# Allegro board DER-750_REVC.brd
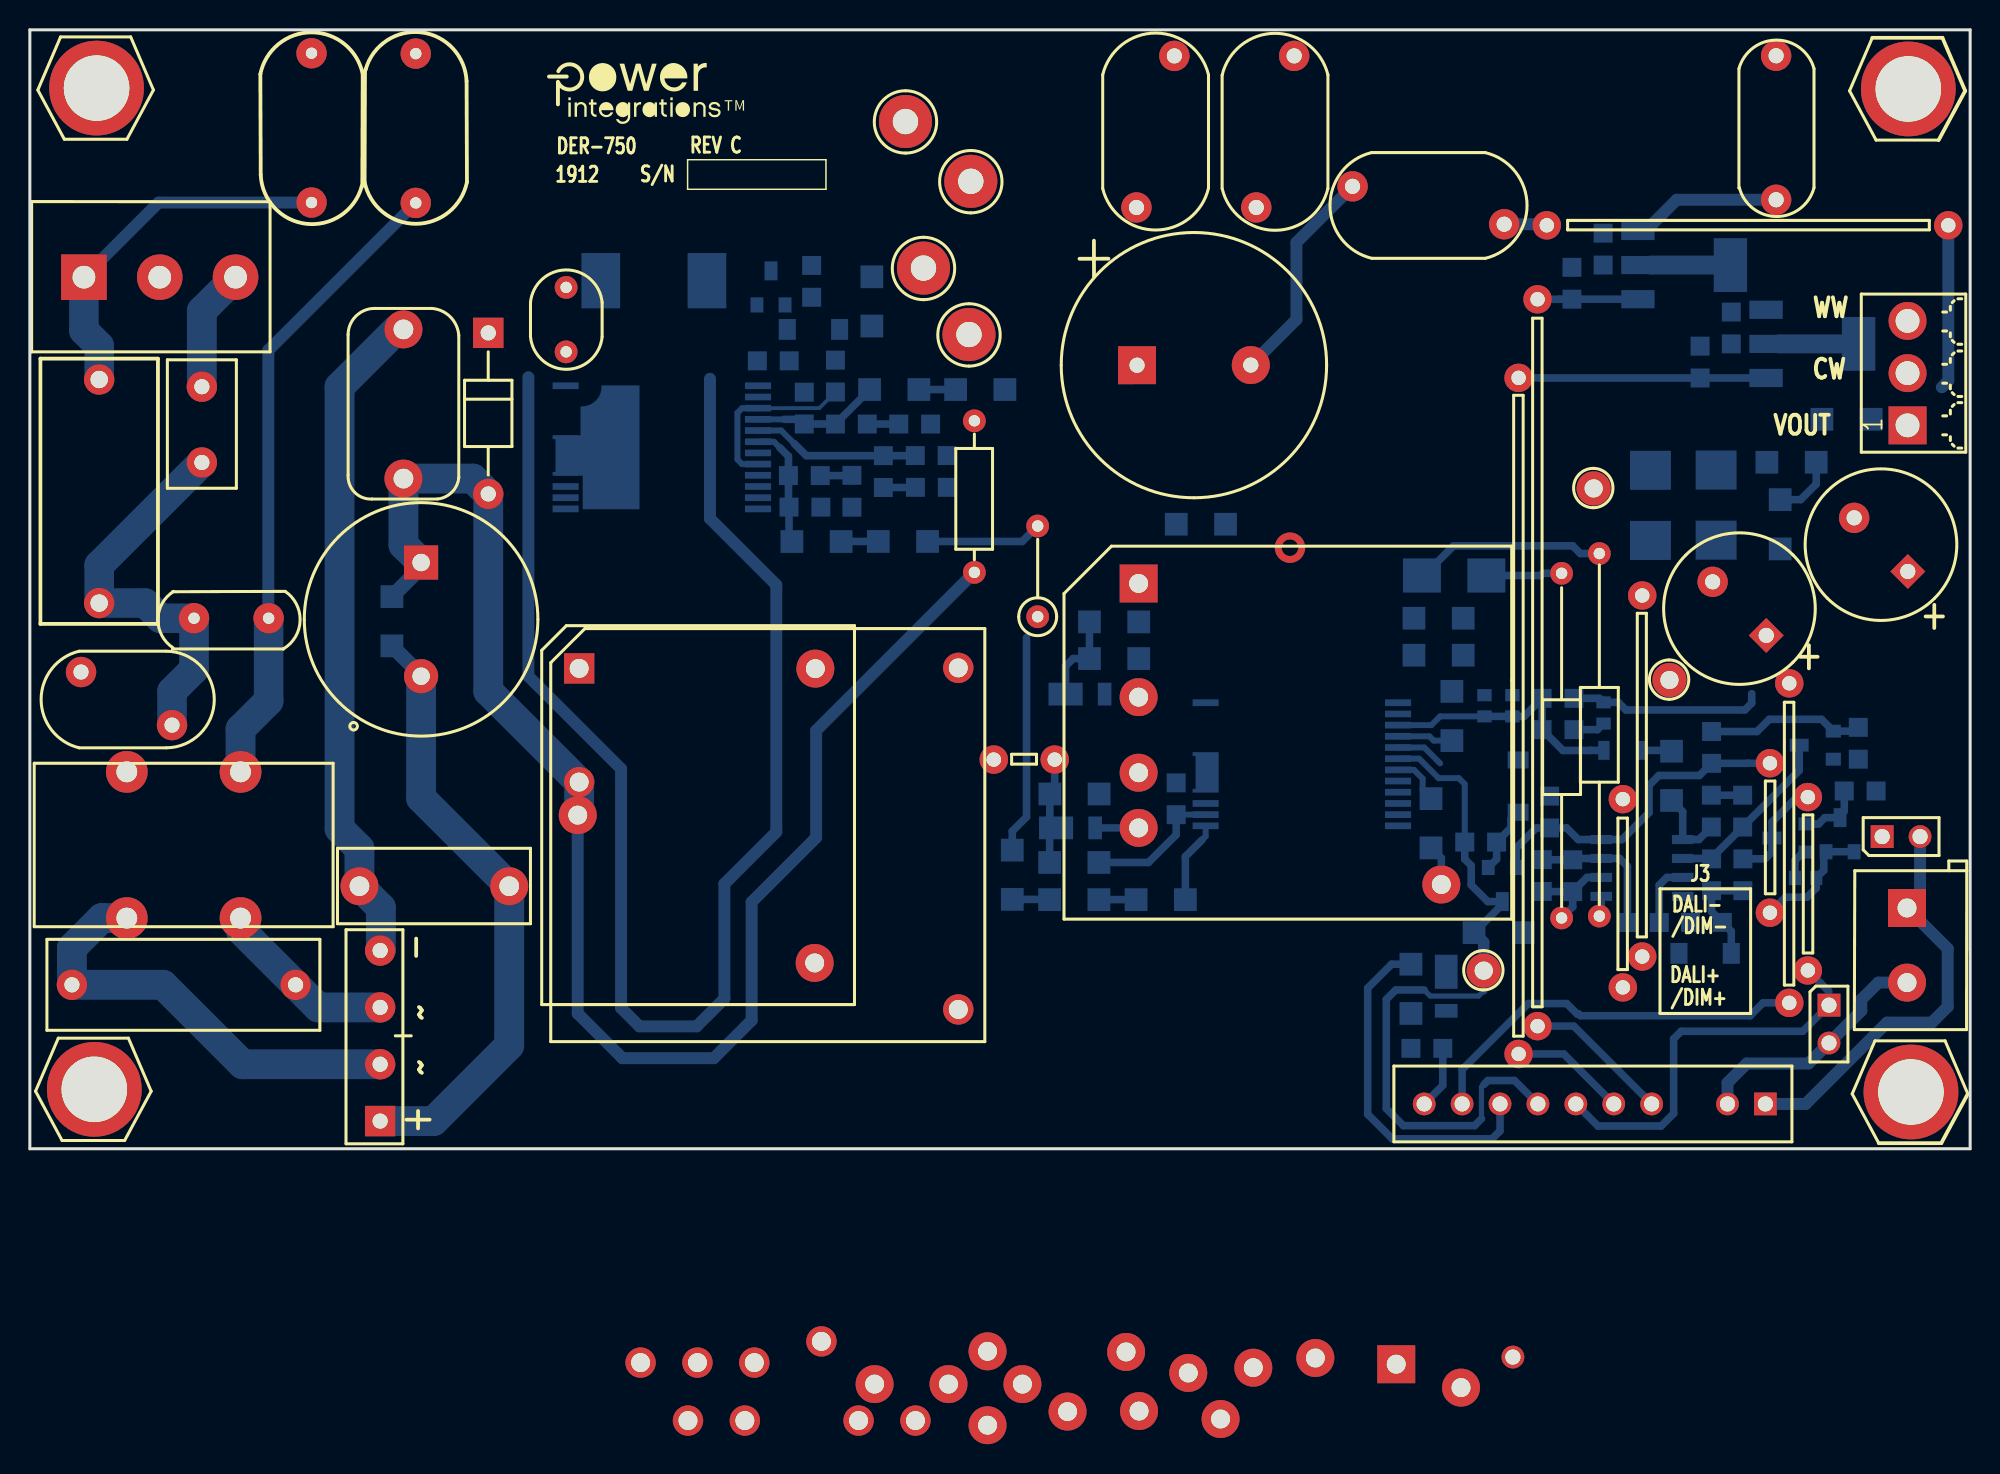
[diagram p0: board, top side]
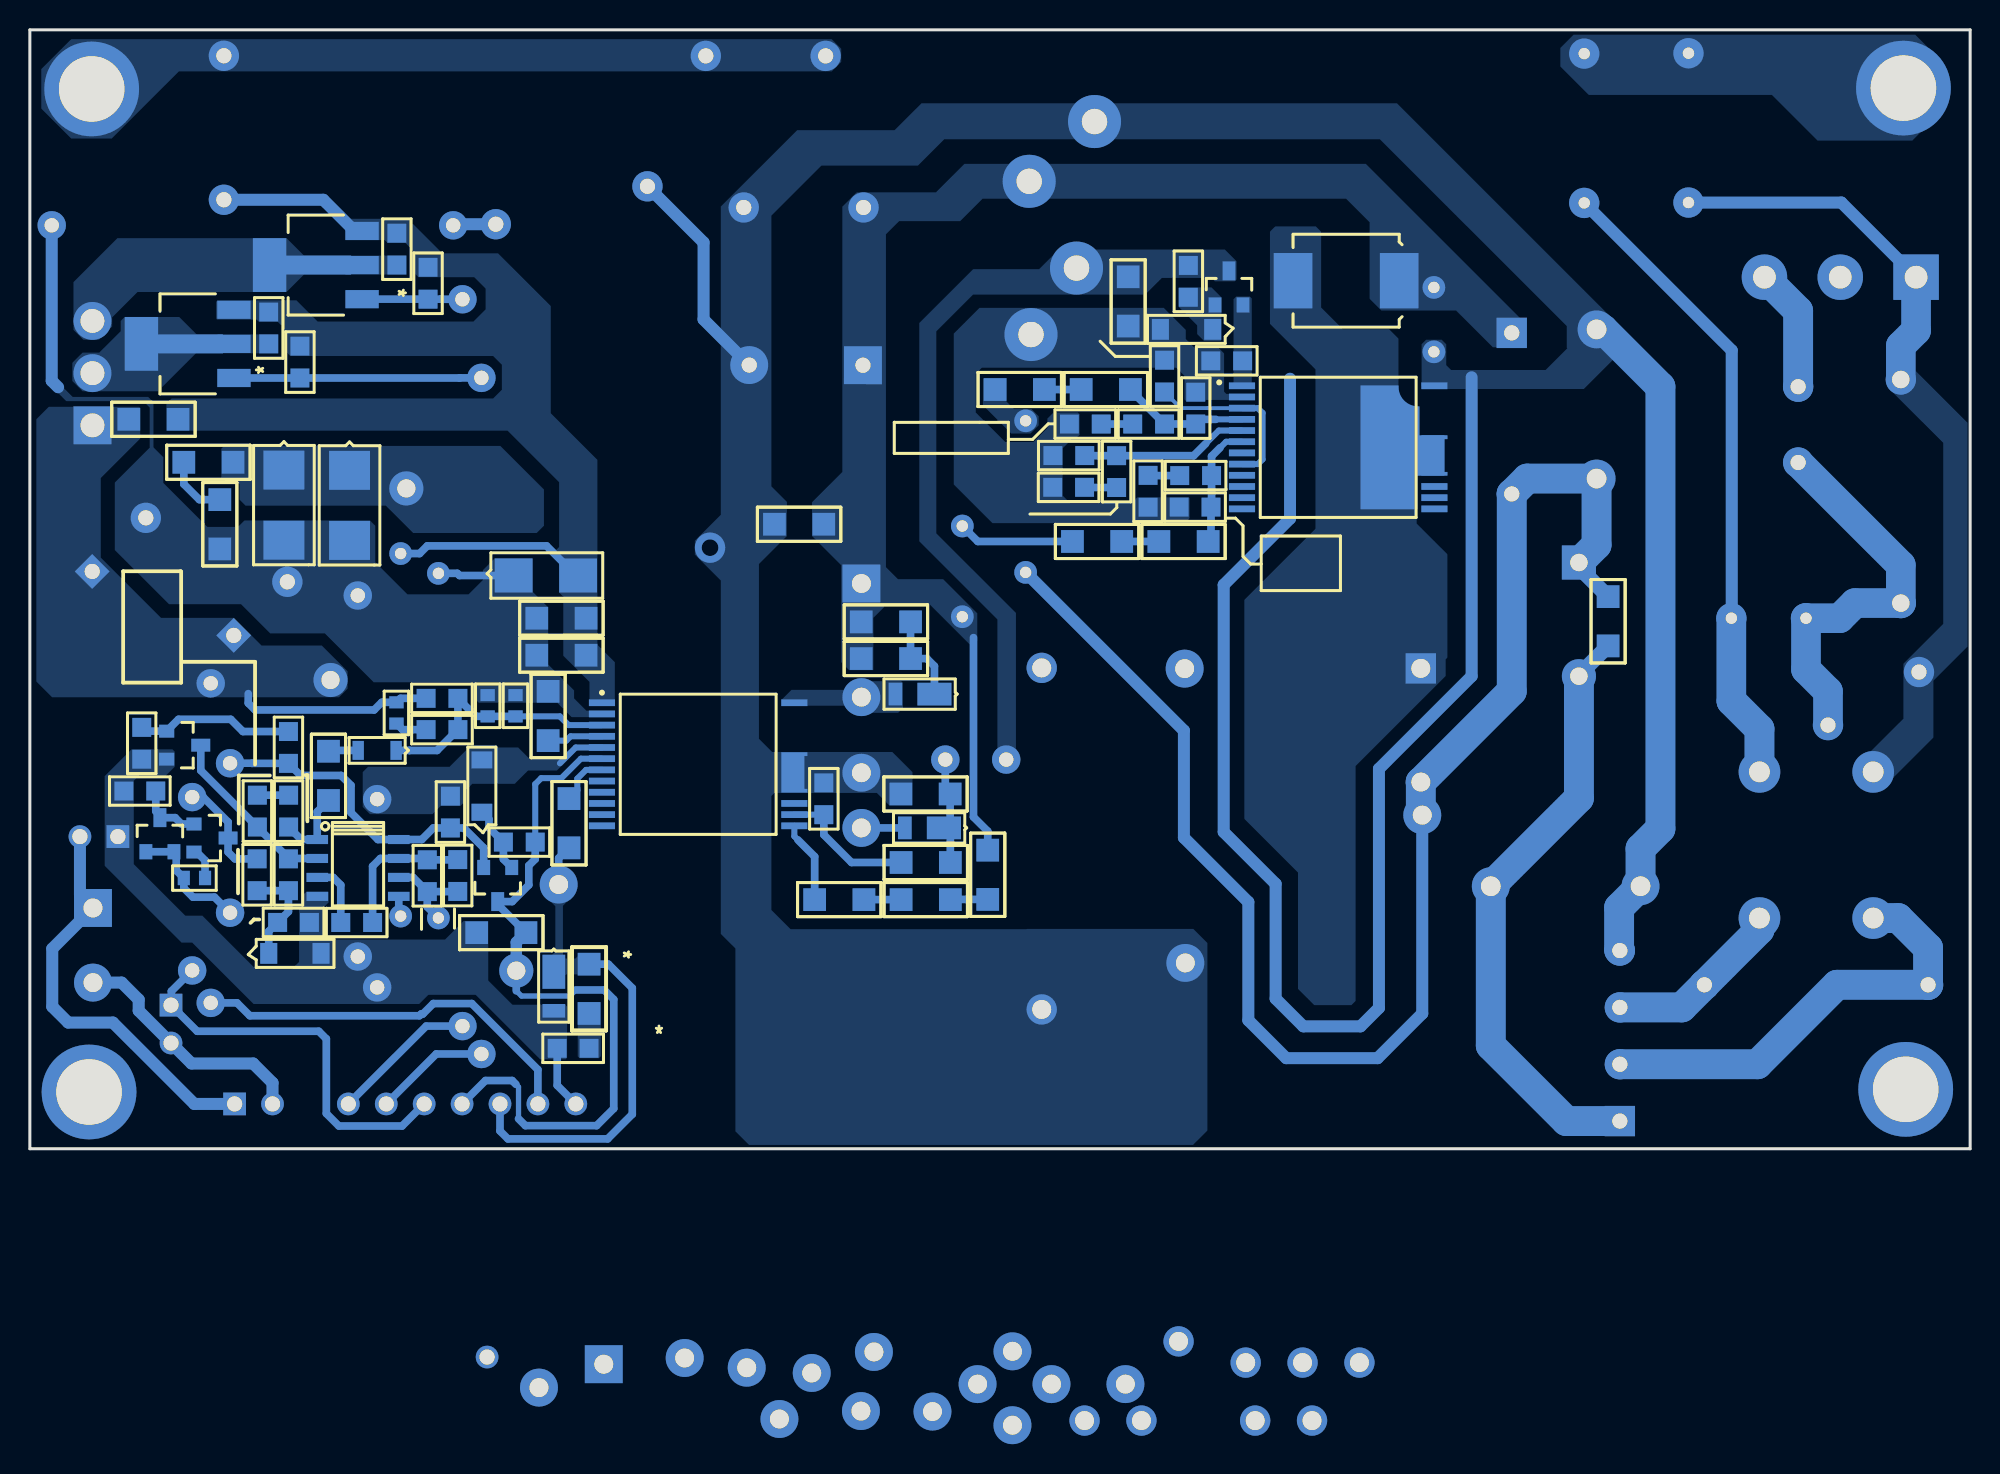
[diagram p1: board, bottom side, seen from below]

Outline 130 x 75 mm; copper layers: TOP, BOTTOM. Coordinates in mm from the lower left corner of the outline.
Outline path: 0,75 130,75 130,0 0,0 0,75

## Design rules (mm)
constraint set DEFAULT: min track width 0.508

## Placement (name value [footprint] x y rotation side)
BR1  UD4KB100-BP  [PIDAXBRIDGED3K]  23.47 1.85 90 top
C1  100 nF  [PI_NP_XCAP_RAD512X197X395D040]  32.12 17.6 180 top
C2  330 nF  [PI_NP_CAPRAD512X299LS394D040]  25.03 44.92 90 top
C3  220 nF  [PINPXCAPRAD710X315590046]  4.64 36.58 90 top
C4  150 nF  [PINPXCAPRAD720X240590040]  2.82 10.99 0 top
C5  6.8 nF  [PISMC0603]  105.44 29.92 270 bottom
C6  100 nF  [PISMC1206]  123.37 48.9 180 bottom
C7  330 uF  [PIPOLCAPCYLD400LS200040]  116.34 34.41 135 top
C8  330 uF  [PIPOLCAPCYLD400LS200040]  125.82 38.7 135 top
C9  1000 pF  [PISMC1206]  70.99 35.32 0 bottom
C10  220 pf  [PISMC1206]  117.27 43.51 270 bottom
C11  330 pF  [PINPYCAPRAD470X210LS380040]  117 63.61 90 top
C12  3.3 nF  [PINPYCAPRAD540X290LS400040]  88.62 64.51 0 top
C13  82 uF  [PIPOLCAPCLYD710LS300040]  74.18 52.52 0.1 top
C14  10 nF  [PI_NP_CAP250X200LS170D030]  35.93 57.73 270 top
C15  330 pF  [PISMC0603]  97.46 30.4 270 bottom
C16  2.2 uF  [PISMC1206]  95.28 30.66 270 bottom
C17  1 uF  [PISMC0805]  53.98 50.72 90 bottom
C18  1 uF  [PISMC0805]  48.74 52.81 0 bottom
C19  470 pF  [PISMC0805]  50.86 43.01 0 bottom
C20  10 uF  [PISMC1206]  56.41 58.45 270 bottom
C21  470 pF  [PISMC0805]  51.89 48.58 90 bottom
C22  100 nF  [PISMC0805]  59.32 46.46 0 bottom
C23  1 uF  [PISMC0805]  59.33 44.33 0 bottom
C25  2.2 uF  [PISMC0805]  112.67 27.97 270 bottom
C26  10 uF  [PISMC1206]  68.34 23.78 0 bottom
C27  0.47 uF  [PISMC0805]  76.8 22.39 90 bottom
C28  0.47 uF  [PISMC0805]  112.66 21.56 90 bottom
C29  3.3 uF  [PISMC0805]  111.27 15.17 0 bottom
C30  1 nF  [PISMC0805]  103.37 17.23 90 bottom
C31  10 uF  [PISMC1206]  96.76 14.48 0 bottom
C32  100 nF  [PISMC0805]  101.82 21.5 90 bottom
C34  2200 pF  [PINPCAPRAD394X275394030]  25.86 63.4 90 top
C35  2200 pF  [PINPCAPRAD394X275394030]  18.87 73.43 270 top
C36  10 nF  [PISMC1206]  76.81 41.86 0 bottom
C37  3.3 nF  [PINPYCAPRAD540X290LS400040]  74.14 63.09 90 top
C38  3.3 nF  [PINPYCAPRAD540X290LS400040]  84.71 73.25 270 top
C39  220 pF  [PISMC0805]  92.53 6.73 0 bottom
D2  1N4006  [PIDV200X110X040DO41]  30.71 54.69 270 top
D3  DFLR1600-7  [PISMDDFLR120012]  69.37 30.47 180 bottom
D4  ES2G-13-F  [PISMDO214AA12]  112.98 45.49 270 bottom
D5  STTH3R06S  [PISMDO214AB12]  38.25 58.18 0 bottom
D7  DFLR1400-7  [PISMDDFLR120012]  68.73 21.51 180 bottom
D9  B340A-13-F  [PISMDO214AC12]  97.59 38.42 180 bottom
D11  DFLU1200-7  [PISMDDFLR120012]  94.89 11.89 90 bottom
D13  ES2G-13-F  [PISMDO214AA12]  108.58 45.47 270 bottom
D14  BAS21HT1G  [PISMSOD323]  105.46 26.7 0 bottom
F1  3.15 A  [PI_RST_MICROFUSE]  11.52 51.08 270 top
FL1  Hole_50mils  [PI_HOLE_50MIL]  109.86 31.42 0 top
FL2  Hole_50mils  [PI_HOLE_50MIL]  104.78 44.26 0 top
FL3  Hole_50mils  [PI_HOLE_50MIL]  97.41 11.94 0 top
J1  TERMINAL BLOCK  [PI_TERM_BLOCK_3PIN]  3.62 58.42 270 top
J2  CON3  [PI_HDR_3PIN_PHOENIX_3P5LS100D]  125.81 48.49 90 top
J3  TERMINAL BLOCK  [PI_TERM_BLOCK_2PIN_LS200]  125.77 16.14 180 top
J4  CON2  [PIMOLEX2KKHEADER]  120.54 9.63 270 top
J5  CON2  [PIMOLEX2KKHEADER]  124.1 20.92 0 top
J7  CON10  [PI_MOLEX_10]  116.28 3 180 top
JP1  J  [PI_JUMPER200]  64.08 26.09 0 top
JP2  J  [PI_JUMPER300#3]  108.92 61.9 0 top
JP3  J  [PI_JUMPER300#4]  117.88 8.08 90 top
JP4  J  [PI_JUMPER300#7]  119.13 23.57 270 top
JP5  J  [PI_JUMPER1000]  108.03 37.08 270 top
JP6  J  [PI_JUMPER300#2]  106.73 8.81 90 top
JP7  J  [PI_JUMPER300#6]  101.02 7.62 90 top
JP8  J  [PI_JUMPER300]  116.59 18.44 270 top
JP9  J  [PI_JUMPER300#5]  99.75 9.65 90 top
L1  18 mH  [PI_IND_4P_690X512LS300X200D055]  14.12 22.9 270 top
L2  1 mh  [PI_CHOKE_RL5480-5_D2]  26.21 39.29 270 top
NOREF  -  []  130 0 90 top
NOREF#2  -  []  34.67 73.25 0 top
NOREF#3  -  []  0 0 0 top
Q1  MMBTA06LT1G  [PISMSOT23123_1]  48.72 56.56 180 bottom
Q3  MMBT3906  [PISMSOT23123_1]  119.01 19.89 270 bottom
Q5  2N7002  [PISMSOT23123_1]  120.83 26.11 270 bottom
Q6  MMBTA06LT1G  [PISMSOT23123_1]  99.59 18.85 0 bottom
Q7  ZXMN6A09GTA  [PISMSOT2231234]  122.52 53.95 90 bottom
Q8  ZXMN6A09GTA  [PISMSOT2231234]  113.94 59.23 90 bottom
R4  100 k  [PISMR0805]  103.45 30.19 180 bottom
R5  1.00 M  [PISMR1206]  74.3 32.86 180 bottom
R6  20  [PISMR1206]  119.68 46.01 180 bottom
R7  3.09 k  [PISMR0603]  99.33 28.98 90 bottom
R8  3.74 M  [PI14WVRESD100LS100D030#2]  67.52 35.66 90 top
R9  6.2 M  [PISMR1206]  60.15 40.7 180 bottom
R10  6.2 M  [PI14WVRESD100LS100D030#4]  63.28 38.63 90 top
R11  6.2 M  [PISMR1206]  65.33 50.89 180 bottom
R12  6.2 M  [PISMR1206]  51.05 40.7 0 bottom
R13  3.74 M  [PISMR1206]  59.56 50.89 180 bottom
R14  20 k  [PISMR0603]  119.68 18.15 180 bottom
R15  30.1 k  [PISMR0805]  57.19 46.46 270 bottom
R17  9.09 k  [PISMR0805]  53.98 48.58 0 bottom
R18  143 k  [PISMR0805]  58.22 48.58 0 bottom
R19  9.09 k  [PISMR0805]  50.83 45.12 0 bottom
R20  143 k  [PISMR0805]  55.08 45.14 270 bottom
R21  10 k  [PISMR1206]  68.33 19.19 0 bottom
R22  46.4 k  [PISMR1206]  109.99 26.64 270 bottom
R23  20.0 k  [PISMR0805]  114.77 17.3 90 bottom
R24  0.068  [PISMR1206]  92.74 33.08 0 bottom
R27  10 k  [PISMR0805]  121.56 23.98 0 bottom
R29  10 k  [PISMR0805]  122.5 28.24 270 bottom
R30  47  [PISMR1206]  93.88 20.17 90 bottom
R31  0.068  [PISMR1206]  92.74 35.56 0 bottom
R32  10 k  [PISMR0805]  114.76 21.56 90 bottom
R34  267 k  [PISMR0805]  101.33 19.38 270 bottom
R37  1 k  [PI14WVRESD100LS100D030]  105.16 15.6 90 top
R38  1 k  [PI14WVRESD100LS100D030#3]  102.63 15.47 90 top
R39  1.00 k  [PISMR0805]  109.17 15.16 180 bottom
R41  1.00 k  [PISMR0805]  112.67 19.43 270 bottom
R43  20.0 k  [PISMR0805]  103.45 28.09 180 bottom
R45  1.00 M  [PISMR1206]  65.82 20.02 270 bottom
R46  1.00 M  [PISMR1206]  68.33 16.7 0 bottom
R47  1.91 M  [PISMR1206]  74.12 16.7 0 bottom
R50  30 k  [PISMR0805]  52.38 59.21 270 bottom
R53  30 k  [PISMR0805]  96.14 20.55 0 bottom
R55  20 k  [PISMR0805]  111.91 51.66 90 bottom
R57  20 k  [PISMR0805]  103.32 56.95 90 bottom
R58  10.0 k  [PISMR1206]  24.26 33.71 90 bottom
R59  0.0  [PISMR0805]  114 53.95 90 bottom
R60  0.0  [PISMR0805]  105.41 59.23 90 bottom
R61  20  [PISMR1206]  92.53 9.07 90 bottom
RT1  2.5  [PI_RAD150X300LS200D030]  11 35.56 0 top
RV1  300 Vac  [PIDISC350X225LS240X140040]  9.53 28.4 180 top
STDOFF1  Standoff Hex, 6-32, .375L, F/F, NYL, 94V-0  [PI_STANDOFF_6_32]  4.47 71.09 0 top
STDOFF2  Standoff Hex, 6-32, .375L, F/F, NYL, 94V-0  [PI_STANDOFF_6_32]  4.32 3.98 0 top
STDOFF3  Standoff Hex, 6-32, .375L, F/F, NYL, 94V-0  [PI_STANDOFF_6_32]  125.86 71.04 0 top
STDOFF4  Standoff Hex, 6-32, .375L, F/F, NYL, 94V-0  [PI_STANDOFF_6_32]  126.03 3.8 0 top
T1  RM8  [PI_BOBBIN_RM8_12P]  74.29 37.89 0 top
T2  EE25  [PI_BOBBIN_EE25_10P]  36.71 32.27 0 top
T3  PQ26/20  [PI_BOBBIN_BPQ26_20_12P]  36.8 32.2 0 top
TP3  CON1  [PITPKEYSTONE125X125]  63.04 64.85 0 top
TP4  CON1  [PITPKEYSTONE125X125]  59.87 59.03 0 top
TP5  CON1  [PITPKEYSTONE125X125]  62.92 54.58 0 top
TP6  CON1  [PITPKEYSTONE125X125]  58.67 68.85 0 top
U2  PFS76X3C  [PI_IC_INSOP24B]  42.34 47.02 180 bottom
U3  LM431BIM3/NOPB  [PISMSOT23123]  120.35 19.91 180 bottom
U4  LYT6067C  [PI_IC_INSOP_24D]  91.67 29.9 180 bottom
U5  TSX712IDT  [PISMSO8]  110.74 20.73 270 bottom
VR1  MMSZ4700T1G  [PI_SM_SOD-123_12]  50.75 54.92 0 bottom
VR2  MMSZ5242B-7-F  [PI_SM_SOD-123_12]  114 13.1 180 bottom
VR3  MMSZ4700T1G  [PI_SM_SOD-123_12]  99.71 22.56 90 bottom

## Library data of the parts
BR1 = DISCRETE BRIDGE_+~~-: alternate symbols: (pidaxbridgeD3K_horz)
C1 C3-C6 C9-C11 C14-C19 C21-C23 C25 C27-C32 C36 C39 = CAP NP
C2 = CAP NP: alternate symbols: (pi_np_caprad512x299ls394d040_h)
C7 C8 = CAP POL
C12 C37 C38 = CAP NP: alternate symbols: (pinpycaprad540x290ls400040h)
C13 = CAP POL: alternate symbols: (pi_cap_cly_d710_ls300_040_1035h)
C20 C26 = CAP NP: alternate symbols: (pismc1206_1)
C34 C35 = CAP NP: alternate symbols: (pinpycaprad500x220ls400040)
D2 = DIODE: alternate symbols: (pidax475x125040do41,pidv200x110x040do41wbead,pidax390x125040do41)
D3-D5 D7 D11 D13 = DIODE
D9 = DIODE SCHOTTKY
D14 = DIODE: alternate symbols: (pismsod323_1)
F1 = FUSE: alternate symbols: (pirstmicrofusehoz)
FL1-FL3 = FlyingLead
J1 J2 = CON3
J3-J5 = CON2
J7 = CON10
JP1-JP9 = JUMPER_1
L1 = CMC_ 4P_12_43: alternate symbols: (pi_4p_700x400d055_horiz)
L2 = INDUCTOR_dot2: alternate symbols: (pi_choke_RL5480-5H_d2)
Q1 Q6 = NPN_BEC
Q3 = PNP_BEC
Q5 = FET_N_GSD
Q7 Q8 = FET_N_GDSD
R4-R7 R9 R11-R15 R17-R24 R27 R29-R32 R34 R39 R41 R43 R45-R47 R50 R53 R55 R57 R58 R61 = R
R8 R10 R37 R38 = R: alternate symbols: (pi14wvresd100ls200d030,pi14wresd100ls400d030,pi14wresd100ls500d030)
R59 R60 = R: alternate symbols: (pismr0805_1)
RT1 = THERMISTOR: alternate symbols: (pirad400x300ls200040_h)
RV1 = VARISTOR
STDOFF1-STDOFF4 = STDOFF_HEX_6-32
T1 = BRM8_12P/GENERIC: alternate symbols: (pi_bobbin_rm8_12p_inline_clp)
T2 = BEE25_10P/GENERIC
T3 = BPQ26/20_12P/GENERIC
TP3-TP6 = TESTPOINT
U2 = DEV_HiperPFS7_inSOP
U3 = TL431/SOT-23_CAR
U4 = LYT6
U5 = TSX712IDT
VR1-VR3 = DIODE_ZENER

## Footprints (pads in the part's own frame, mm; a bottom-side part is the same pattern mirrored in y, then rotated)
PI14WVRESD100LS100D030
  round 1.524 hole 0.762: 1(0,0) 2(24.3,0)
PI14WVRESD100LS100D030#2
  round 1.524 hole 0.762: 1(0,0) 2(6.08,0)
PI14WVRESD100LS100D030#3
  round 1.524 hole 0.762: 1(0,0) 2(23.1,0)
PI14WVRESD100LS100D030#4
  round 1.524 hole 0.762: 1(0,0) 2(10.16,0)
PI_BOBBIN_BPQ26_20_12P
  rect 2.032x2.032 hole 1.27: 1(0,0)
  round 2.032 hole 1.27: 2(16.231,-45.11) 3(0,-7.62) 4(4.115,-46.533) 5(7.925,-46.533) 6(11.735,-46.533) 7(25.4,-22.86) 8(22.53,-50.419) 9(18.72,-50.419) 10(11.1,-50.419) 11(7.29,-50.419) 12(25.4,0.035)
PI_BOBBIN_EE25_10P
  rect 2.54x2.54 hole 1.27: 1(54.839,-46.711)
  round 2.54 hole 1.27: 2(32.817,-49.886) 3(0,-9.906) 4(27.457,-45.847) 5(27.457,-50.8) 6(15.875,-19.812) 7(29.795,-48.045) 8(24.842,-48.045) 9(19.889,-48.045) 10(15.92,-0.086)
PI_BOBBIN_RM8_12P
  rect 2.54x2.54 hole 1.27: 1(0,0)
  round 2.54 hole 1.27: 2(-0.838,-51.511) 3(0,-7.62) 4(0,-12.687) 5(0,-16.385) 6(3.327,-52.921) 7(20.282,-20.18) 8(21.603,-53.901) 9(7.684,-52.568) 10(11.842,-51.918) 11(0.031,-55.474) 12(5.492,-56.007)
PI_CHOKE_RL5480-5_D2
  rect 2.286x2.286 hole 1.168: 1(0,0)
  round 2.286 hole 1.168: 2(7.62,0)
PI_HDR_3PIN_PHOENIX_3P5LS100D
  rect 2.54x2.54 hole 1.6: 1(0,0)
  round 2.54 hole 1.6: 2(3.5,0) 3(7,0)
PI_HOLE_50MIL
  round 2.286 hole 1.219: 1(0,0)
PI_IC_INSOP24B
  rect 1.75x0.45 smd: 1(-6.445,4.125) 2(-6.445,3.375) 3(-6.445,2.625) 4(-6.445,1.875) 5(-6.445,1.125) 6(-6.445,0.375) 7(-6.445,-0.375) 8(-6.445,-1.125) 9(-6.445,-1.875) 10(-6.445,-2.625) 11(-6.445,-3.375) 12(-6.445,-4.125) 13(6.445,-4.125) 14(6.445,-3.375) 15(6.445,-2.625) 24(6.445,4.125)
  custom 0.438x0.438 smd: 16(6.445,-0.545)
PI_IC_INSOP_24D
  rect 1.75x0.45 smd: 1(0,0) 2(0,-0.75) 3(0,-1.5) 4(0,-2.25) 5(0,-3) 6(0,-3.75) 7(0,-4.5) 8(0,-5.25) 9(0,-6) 10(0,-6.75) 11(0,-7.5) 12(0,-8.25) 13(12.89,-8.25) 14(12.89,-7.5) 15(12.89,-6.75) 24(12.89,0)
  custom 0.438x0.438 smd: 16(12.89,-4.67)
PI_IND_4P_690X512LS300X200D055
  round 2.794 hole 1.397: 1(-2.36,0) 2(7.44,0) 3(7.44,-7.62) 4(-2.36,-7.62)
PI_JUMPER200
  round 1.905 hole 0.965: 1(0.5,0) 2(4.58,0)
PI_JUMPER300
  round 1.905 hole 0.965: 1(-7.4,0) 2(2.62,0)
PI_JUMPER300#2
  round 1.905 hole 0.965: 1(2,0) 2(14.62,0)
PI_JUMPER300#3
  round 1.905 hole 0.965: 1(-7.28,0) 2(19.62,0)
PI_JUMPER300#4
  round 1.905 hole 0.965: 1(1.7,0) 2(23.12,0)
PI_JUMPER300#5
  round 1.905 hole 0.965: 1(-3.3,0) 2(42.02,0)
PI_JUMPER300#6
  round 1.905 hole 0.965: 1(0.6,0) 2(49.32,0)
PI_JUMPER300#7
  round 1.905 hole 0.965: 1(0,0) 2(11.62,0)
PI_JUMPER1000
  round 1.905 hole 0.965: 1(0,0) 2(24.2,0)
PI_MOLEX_10
  rect 1.524x1.524 hole 1.016: 1(0,0)
  round 1.524 hole 1.016: 2(2.54,0) 3(16.916,16.967) 4(7.62,0) 5(10.16,0) 6(12.7,0) 7(15.24,0) 8(17.78,0) 9(20.32,0) 10(22.86,0)
PI_NP_CAP250X200LS170D030
  round 1.524 hole 0.762: 1(0,0) 2(4.318,0)
PI_NP_CAPRAD512X299LS394D040
  round 2.54 hole 1.321: 1(0,0) 2(10,0)
PI_NP_XCAP_RAD512X197X395D040
  round 2.54 hole 1.321: 1(0,0) 2(10.033,0)
PI_RAD150X300LS200D030
  round 2.032 hole 0.762: 1(0,0) 2(5,0)
PI_RST_MICROFUSE
  round 2.032 hole 1.016: 1(0,0) 2(5.08,0)
PI_SM_SOD-123_12
  rect 1.143x1.397 smd: 1(0,0) 2(3.505,0)
PI_STANDOFF_6_32
  round 6.35 hole 4.394: 1(0,0)
PI_TERM_BLOCK_2PIN_LS200
  rect 2.54x2.54 hole 1.27: 1(0,0)
  round 2.54 hole 1.27: 2(0,5.001)
PI_TERM_BLOCK_3PIN
  rect 3.048x3.048 hole 1.524: 1(0,0)
  round 3.048 hole 1.524: 2(0,5.08) 3(0,10.16)
PIDAXBRIDGED3K
  rect 2.032x2.032 hole 1.016: 1(0,0)
  round 2.032 hole 1.016: 2(3.81,0) 3(7.62,0) 4(11.43,0)
PIDISC350X225LS240X140040
  round 2.032 hole 1.016: 1(0,0) 2(6.096,-3.556)
PIDV200X110X040DO41
  rect 2.032x2.032 hole 1.016: 1(0,0)
  round 2.032 hole 1.016: 2(10.795,0)
PIMOLEX2KKHEADER
  rect 1.524x1.524 hole 1.016: 1(0,0)
  round 1.524 hole 1.016: 2(2.54,0)
PINPCAPRAD394X275394030
  round 2.032 hole 0.762: 1(0,0) 2(10.008,0)
PINPXCAPRAD710X315590046
  round 2.032 hole 1.168: 1(0,0) 2(14.986,0)
PINPXCAPRAD720X240590040
  round 2.032 hole 1.016: 1(0,0) 2(14.986,0)
PINPYCAPRAD470X210LS380040
  round 2.032 hole 1.016: 1(0,0) 2(9.652,0)
PINPYCAPRAD540X290LS400040
  round 2.032 hole 1.016: 1(0,0) 2(10.16,-2.54)
PIPOLCAPCLYD710LS300040
  rect 2.54x2.54 hole 1.016: 1(0,0)
  round 2.54 hole 1.016: 2(7.62,0)
PIPOLCAPCYLD400LS200040
  rect 1.651x1.651 hole 1.016: 1(0,0)
  round 2.032 hole 1.016: 2(5.08,0)
PISMC0603
  rect 0.813x0.965 smd: 1(0,0) 2(1.422,0)
PISMC0805
  rect 1.27x1.27 smd: 1(0,0) 2(2.134,0)
PISMC1206
  rect 1.524x1.524 smd: 1(0,0) 2(3.302,0)
PISMDDFLR120012
  rect 2.286x1.524 smd: 1(-0.025,0)
  rect 0.914x1.524 smd: 2(-2.642,0)
PISMDO214AA12
  rect 2.616x2.743 smd: 1(0,0) 2(4.699,0)
PISMDO214AB12
  rect 2.591x3.708 smd: 1(0,0) 2(7.112,0)
PISMDO214AC12
  rect 2.54x2.286 smd: 1(0,0) 2(4.318,0)
PISMR0603
  rect 0.813x0.965 smd: 1(0,0) 2(1.422,0)
PISMR0805
  rect 1.27x1.27 smd: 1(0,0) 2(2.134,0)
PISMR1206
  rect 1.524x1.524 smd: 1(0,0) 2(3.302,0)
PISMSO8
  rect 0.61x1.448 smd: 1(0,0) 2(1.27,0) 3(2.54,0) 4(3.81,0) 5(3.81,5.461) 6(2.54,5.461) 7(1.27,5.461) 8(0,5.461)
PISMSOD323
  rect 0.762x1.27 smd: 1(0,0) 2(2.54,0)
PISMSOT23123
  rect 0.864x1.016 smd: 1(-1.88,0) 3(0,0)
  rect 0.864x1.27 smd: 2(-0.94,2.286)
PISMSOT23123_1
  rect 0.864x1.016 smd: 1(-1.88,0) 2(0,0)
  rect 0.864x1.27 smd: 3(-0.94,2.286)
PISMSOT2231234
  rect 1.219x2.235 smd: 1(-2.286,-6.198) 2(0,-6.198) 3(2.286,-6.198)
  rect 3.607x2.235 smd: 4(0,0)
PITPKEYSTONE125X125
  round 3.556 hole 1.702: 1(0,0)

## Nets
GND1: C32.2 JP6.2 U4.5 VR3.2
GND_EARTH: C11.2 C37.2 C38.1 STDOFF3.1
15 VDC AUX: C20.1 JP1.1 Q1.3 R50.1 TP4.1
CW: J2.2 Q7.2 Q7.4 R59.1
CW GATE: JP9.2 Q7.1 R55.1
DALI +/ DIM +: J3.2 J4.2 J7.2
DALI -/ DIM -: J3.1 J5.2 J7.1
DIM-: C29.1 C31.2 C39.2 D11.2 J5.1 J7.10 JP5.2 JP6.1 Q5.2(S) R27.2 R29.2 U5.4 VR2.2
FB_PIN: C15.2 D14.1 R4.2 R7.1 R43.2 U4.3
IS: C6.2 C11.1 D9.2 Q7.3(S) Q8.3(S) R24.1 R31.1 R37.2 R55.2 R57.2 R59.2 R60.2 U4.1
NC8: U4.8
NC9: U2.9 U4.9
NC10: U2.10 U4.10
NC11: U2.11 U4.11
NC12: U2.12 U4.12
NC13: U2.13
NC14: U2.14
NC15: U2.15 U4.15
PWM: J4.1 J7.6 JP4.2
RS-: C7.2 C8.2 C10.2 C15.1 C16.1 D4.2 D9.1 D13.2 JP2.2 JP5.1 R7.2 R24.2 R31.2 R38.2 U4.2
RTN: BR1.4 C1.2 C2.2 C12.1 C13.2 C14.2 C26.2 C27.2 C36.2 C38.2 T1.4 T2.6 T3.7 TP6.1 U2.24 U4.16
SEC BIAS 1: D11.1 J7.8 R30.1 R61.2 T1.7
STAND DCDC: T1.12
STAND PFC 1: T3.12
STAND PFC 2: T2.10
V_AUX: C31.1 FL3.1 J7.7 Q6.3 R53.1 U4.6
V_O: C5.1 C6.1 C7.1 C8.1 FL1.1 J2.1 JP3.2 R4.1
VRECT: C2.1 D2.2 L2.1 R10.1 R58.2 T2.3 T3.3
WW: J2.3 Q8.2 Q8.4 R60.1
WW GATE: JP7.2 Q8.1 R57.1
Y1Y2: C34.2 C35.1 STDOFF1.1
N11473952: BR1.1 C1.1 L2.2 R58.1
N11474046: F1.1 J1.3
N11474074: C3.1 F1.2 RT1.1 RV1.1
N11474232: C3.2 C35.2 J1.1 L1.4 RV1.2
N11475153: C9.2 C13.1 C14.1 C36.1 C37.1 D2.1 D5.1 R5.1 R8.1 R45.1 T1.1 TP3.1
N11476179: D5.2 T2.1 T3.1 U2.16
N11479125: C18.1 Q1.2(EMITTER) U2.1(VCC)
N11479543: C19.1 R12.1 R19.1 U2.6
N11479547: C22.1 R15.1 U2.5
N11479611: C23.1 R15.2
N11479651: C17.2 C18.2 C19.2 C20.2 C21.2 C22.2 C23.2 R18.2 R20.2 TP5.1 U2.2 VR1.2
N11480020: C21.1 R13.2 R17.1 U2.4
N11480864: R10.2 R11.1
N11480868: R11.2 R13.1
N11481429: C17.1 U2.3 U2.8
N11482333: R9.2 R12.2
N11498937: D4.1 D13.1 FL2.1 R6.2
N11498945: C9.1 D3.1 R5.2
N11499175: C10.1 R6.1
N11499187: D7.2 T1.5
N11499225: D3.2 T1.3 U4.24
N11499449: C26.1 D7.1 JP1.2 R21.1
N11499609: R30.2 U4.7
N11499647: R47.2 U4.13(VPIN)
N11499655: C16.2 U4.4
N11499799: C27.1 R21.2 U4.14
N11939314: R19.2 R20.1
N11939723: R17.2 R18.1
N11948429: R45.2 R46.1
N11948437: R46.2 R47.1
N12019643: T1.6
N12022540: C12.2 JP2.1
N12100407: C25.2 C32.1 JP8.1 Q6.2(EMITTER) U5.8
N12100435: JP8.2 R14.1 U3.1 U3.3(VREF)
N12100443: Q3.2(EMITTER) R14.2
N12100467: Q6.1 R53.2 VR3.1
N12100553: Q3.1 R27.1 U3.2
N12100613: JP4.1 Q3.3 R23.2
N12100617: C25.1 Q5.1 R29.1
N12100771: R39.1 U5.3
N12100779: Q5.3 R32.1 R41.1 U5.2
N12100795: C29.2 R23.1 R41.2 VR2.1
N12100835: D14.2 R22.1
N12100839: C28.1 R22.2 U5.1
N12100987: C28.2 R32.2
N12101111: C30.2 R34.1 R39.2 U5.7(OUT)
N12101185: R37.1 U5.5
N12101201: C30.1 R34.2 R38.1 U5.6
N12102647: Q1.1 R50.2 VR1.1
N12107790: J7.9 JP3.1
N12159127: R8.2 R9.1
N12171260: T1.8
N12184871: C5.2 R43.1
N12192768: C39.1 R61.1
N12236438: BR1.3(AC2) C4.2 L1.2
N12236447: C34.1 L1.1 RT1.2
N12236503: BR1.2 C4.1 L1.3
N12238576: J7.5 JP9.1
N12238603: J7.4 JP7.1

Pads without a net: J1 2; J7 3; STDOFF2 1; STDOFF4 1; T1 2 9 10 11; T2 2 4 5 7 8 9; T3 2 4 5 6 8 9 10 11; U2 7

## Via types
v1: diameter 2.032, hole 1.118, TOP to BOTTOM, 1 via

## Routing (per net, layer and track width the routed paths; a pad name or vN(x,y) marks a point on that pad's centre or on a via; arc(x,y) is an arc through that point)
GND1: length 3.3
  BOTTOM w0.4: 94.49,25.83 93.42,26.9 U4.5
CW GATE: length 16.6
  BOTTOM w0.508: JP9.2 101.21,51.67 101.21,51.66 R55.1 Q7.1
DALI +/ DIM +: length 16.7
  BOTTOM w0.8: J7.2 113.74,4.42 115.04,5.71 119.17,5.71 J4.2 122.71,9.25 122.71,10 123.85,11.14 J3.2
DALI -/ DIM -: length 27.8
  BOTTOM w0.8: J5.2 126.64,17.01 J3.1 128.5,13.41 128.5,9.53 127.43,8.46 124.43,8.46 118.98,3 J7.1
DIM-: length 4.2
  BOTTOM w0.508: J7.10 94.67,4.25 C39.2
FB_PIN: length 17.2
  BOTTOM w0.4: U4.3 93.9,28.4 94.49,28.98 C15.2
  BOTTOM w0.508: C15.2 R7.1 100.11,28.98 R4.2 R43.2 102.72,26.7 104.57,26.7 104.57,26.7 D14.1
IS: length 23
  BOTTOM w0.508: R37.2 103.89,39.9 103.37,40.41 95.38,40.41 93.4,38.42 D9.2
  BOTTOM w0.8: C11.1 110.34,63.61 108.25,61.52 Q8.3
PWM: length 26.8
  BOTTOM w0.508: JP4.2 120.52,10.56 120.52,9.65 J4.1 118.79,7.87 110.64,7.87 110.13,7.37 110.13,2.36 109.3,1.52 105.06,1.52 J7.6
RS-: length 16.1
  BOTTOM w0.508: D9.1 101.21,38.42 101.36,38.57 R38.2
  BOTTOM w0.8: JP2.2 128.54,51.47 128.11,51.04
RTN: length 157.5
  BOTTOM w0.8: 33.4,51.71 33.4,31.67 39.61,25.46 39.61,9.44 40.84,8.2 44.68,8.2 46.53,10.06 46.53,17.75 50.01,21.23 50.01,37.8 45.57,42.24 45.57,51.61 ; C13.2 84.86,55.59 84.86,60.75 C12.1
  BOTTOM w2: C2.2 24.59,54.92 20.75,51.08 20.75,21.45 22.08,20.12 C1.2 23.52,16.16 23.52,13.33 BR1.4
  vias: v1(84.43,40.29)
SEC BIAS 1: length 26.3
  BOTTOM w0.508: J7.8 98.5,1.19 97.97,0.66 91.29,0.66 89.64,2.31 89.64,10.77 91.24,12.37 92.46,12.37 ; R30.1 94.57,19.48 T1.7
V_AUX: length 49.9
  BOTTOM w0.35: 97.43,4.32 97.26,4.14 97.26,2.01 ; 93.42,10.64 93.82,10.24 97.06,10.24 97.41,10.59
  BOTTOM w0.4: R53.1 96.14,24.44 95.74,24.84 94.39,24.84 93.08,26.15 U4.6
  BOTTOM w0.508: C31.1 98.65,16.38 Q6.3 97.68,16.57 96.57,17.68 96.57,18.98 96.14,19.41 R53.1 ; 97.41,10.59 FL3.1 ; J7.7 99.47,4.57 97.69,4.57 97.43,4.32 ; 97.26,2.01 96.8,1.55 92.02,1.55 90.88,2.69 90.88,10.01 91.52,10.64 93.42,10.64
  BOTTOM w0.762: FL3.1 97.41,13.84 C31.1
V_O: length 13.1
  BOTTOM w0.508: 115.37,30.51 115.37,29.87 114.91,29.41 106.93,29.41 106.43,29.92 C5.1 105.17,30.19 R4.1
VRECT: length 102.9
  BOTTOM w0.8: R10.1 52.68,28.03 52.68,20.85 48.36,16.54 48.36,8.61 45.82,6.07 39.7,6.07 36.71,9.06 T2.3
  BOTTOM w1: R58.2 26.21,38.96 L2.1
  BOTTOM w2: T2.3 36.8,22.46 T3.3 30.71,30.67 D2.2 29.68,44.92 C2.1 25.03,40.48 L2.1
WW GATE: length 6.7
  BOTTOM w0.508: JP7.2 102.48,56.94 102.48,56.95 R57.1 Q8.1
N11473952: length 40.8
  BOTTOM w1: R58.1 26.21,31.75 L2.2
  BOTTOM w2: L2.2 26.21,23.5 C1.1 32.12,6.92 27.05,1.85 BR1.1
N11474046: length 8.3
  BOTTOM w2: J1.3 11.52,56.16 F1.1
N11474074: length 26.8
  BOTTOM w1.981: RV1.1 9.53,30.66 11,32.13 RT1.1 8.74,35.56 7.72,36.58 C3.1 4.64,39.12 F1.2
N11474232: length 24.6
  BOTTOM w0.8: J1.1 8.63,63.42 C35.2
  BOTTOM w1.981: 4.64,51.56 4.64,53.82 3.62,54.84 J1.1
N11475153: length 14.6
  BOTTOM w0.508: 66.78,34.26 66.78,22.24 65.82,21.29 R45.1
N11479543: length 8.3
  BOTTOM w0.4: 50.26,46.98 49.85,47.39 U2.6
  BOTTOM w0.508: 50.26,46.98 50.83,46.42 R19.1 50.83,43.05 C19.1 50.86,40.89 R12.1
N11479547: length 11.2
  BOTTOM w0.4: 51.22,47.26 50.34,48.14 U2.5
  BOTTOM w0.508: 51.22,47.26 52.02,46.46 R15.1 59.32,46.46 C22.1
N11479611: length 2.2
  BOTTOM w0.508: R15.2 59.32,44.32 C23.1
N11480020: length 8.6
  BOTTOM w0.4: 50.55,48.89 U2.4
  BOTTOM w0.508: 50.55,48.89 51.57,48.89 C21.1 53.97,48.58 R17.1 56.26,50.86 R13.2
N11480868: length 2.5
  BOTTOM w0.508: R13.1 R11.2
N11481429: length 11.8
  BOTTOM w0.254: U2.3 51.07,49.64 51.07,49.65 52.9,49.65 C17.1
  BOTTOM w0.4: U2.8 47.72,45.89 47.41,46.21 47.41,49.32 47.72,49.64 U2.3
N11482333: length 2.5
  BOTTOM w0.508: R12.2 54.36,40.7 R9.2
N11498945: length 6.1
  BOTTOM w0.508: C9.1 R5.2 69.9,32.86 69.39,32.35 D3.1
N11499175: length 4.3
  BOTTOM w0.508: R6.1 119.68,44.55 118.64,43.51 C10.1
N11499187: length 2.9
  BOTTOM w0.508: T1.5 71.38,21.51 D7.2
N11499449: length 7.4
  BOTTOM w0.508: R21.1 68.33,21.08 D7.1 68.34,21.93 C26.1 68.66,24.11 JP1.2
N11499609: length 3.5
  BOTTOM w0.4: U4.7 92.73,25.4 93.32,24.81 93.32,24.03 R30.2
N11499647: length 5.5
  BOTTOM w0.4: 78.54,20.7 78.78,20.94 U4.13
  BOTTOM w0.508: R47.2 77.42,19.58 78.54,20.7
N11499655: length 3.7
  BOTTOM w0.4: C16.2 94.06,27.36 93.77,27.65 U4.4
N11499799: length 9.3
  BOTTOM w0.4: C27.1 76.81,22.4 U4.14
  BOTTOM w0.508: C27.1 76.8,21.04 74.95,19.19 R21.2
N11939314: length 2.1
  BOTTOM w0.508: R19.2 55.06,45.12 R20.1
N11939723: length 2.1
  BOTTOM w0.508: R17.2 R18.1
N11948429: length 2.5
  BOTTOM w0.508: R45.2 68.31,16.71 R46.1
N11948437: length 2.5
  BOTTOM w0.508: R47.1 R46.2
N12022540: length 2.9
  BOTTOM w0.8: C12.2 101.56,61.97 JP2.1
N12100407: length 22.4
  BOTTOM w0.508: JP8.1 115.13,25.84 115.12,25.83 C25.2 111.86,25.02 109.14,25.02 108.48,24.36 108.48,22.53 106.68,20.73 U5.8 103.74,20.73 102.97,21.5 C32.1 100.93,21.5 99.59,20.17 Q6.2
N12100435: length 8.4
  BOTTOM w0.508: U3.1 U3.3 120.19,19.76 120.19,18.66 R14.1 119.68,17.48 119.08,16.87 117.63,16.87 JP8.2
N12100443: length 2.2
  BOTTOM w0.508: Q3.2 118.83,19.89 118.26,19.32 R14.2
N12100467: length 4.5
  BOTTOM w0.508: Q6.1 98.27,19.41 R53.2 99.24,21.52 99.24,22.08 VR3.1
N12100553: length 4.4
  BOTTOM w0.508: Q3.1 119.84,21.77 120.27,22.19 121.28,22.19 121.28,22.35 121.56,22.63 R27.1
N12100613: length 7.2
  BOTTOM w0.508: JP4.1 118.39,23.57 116.72,21.9 Q3.3 116.72,19.89 116.26,19.43 R23.2
N12100617: length 10.6
  BOTTOM w0.508: R29.1 122.25,27.99 Q5.1 120.04,28.78 116.54,28.78 115.72,27.97 C25.1
N12100771: length 4.3
  BOTTOM w0.508: U5.3 109.68,18.19 109.17,17.68 R39.1
N12100779: length 12
  BOTTOM w0.508: Q5.3 118.55,25.36 R32.1 112.67,19.48 R41.1 112.65,19.46 U5.2
N12100795: length 6.8
  BOTTOM w0.508: R23.1 R41.2 112.67,15.89 C29.2 114,14.57 VR2.1
N12100835: length 2
  BOTTOM w0.508: R22.1 109.94,26.7 D14.2
N12100839: length 5.2
  BOTTOM w0.508: R22.2 110.74,22.59 U5.1 111.82,20.73 C28.1
N12100987: length 2.1
  BOTTOM w0.508: R32.2 C28.2
N12101111: length 9.7
  BOTTOM w0.508: R39.2 107.04,18.94 106.51,19.46 U5.7 103.46,19.46 C30.2 101.34,19.37 R34.1
N12101185: length 1.4
  BOTTOM w0.508: R37.1 105.28,15.72 U5.5
N12101201: length 6.4
  BOTTOM w0.508: R34.2 101.34,17.23 C30.1 ; C30.1 103.37,16.21 R38.1 ; C30.1 104.32,18.19 U5.6
N12107790: length 26.7
  BOTTOM w0.508: J7.9 95.96,5.3 100.39,9.73 102.97,9.73 103.67,9.03 103.78,9.03 103.9,8.92 115.26,8.92 116.12,9.78 JP3.1
N12159127: length 7.8
  BOTTOM w0.508: R8.2 66.49,40.7 R9.1
N12184871: length 2.1
  BOTTOM w0.508: R43.1 105.03,28.09 C5.2
N12236438: length 12.3
  BOTTOM w2: BR1.3 19.32,9.47 C4.2 14.12,14.68 L1.2
N12236447: length 43
  BOTTOM w0.8: RT1.2 15.97,35.59 15.97,53.51 C34.1
  BOTTOM w1.981: 15.97,29.99 16,30.02 RT1.2
  BOTTOM w2: 15.97,29.99 14.12,28.14 L1.1
N12236503: length 29.8
  BOTTOM w2: L1.3 4.82,15.46 2.82,13.46 C4.1 8.93,10.99 14.25,5.66 BR1.2
N12238576: length 7.8
  BOTTOM w0.508: JP9.1 102.77,6.35 J7.5
N12238603: length 9.8
  BOTTOM w0.508: JP7.1 103.44,8.22 J7.4

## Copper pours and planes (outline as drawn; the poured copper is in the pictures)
GND1 on BOTTOM: 94.36,26.11 96.49,26.11 97.28,26.9 100.58,26.9 101.88,25.6 107.34,25.6 107.7,25.25 107.7,22.91 107.21,22.43 103.02,22.43 102.46,22.99 101.14,22.99 100.79,23.34 100.79,24.03 100.36,24.46 97.51,24.46 96.62,25.35 94.69,25.35 94.26,25.78 94.26,26.01
GND_EARTH on BOTTOM: 127.23,74.37 129.24,72.36 129.24,69.72 127.23,67.72 124.51,67.72 120.02,72.21 76.28,72.21 75.64,72.85 75.64,73.74 76.28,74.37
15 VDC AUX on BOTTOM: 61.06,60.27 49.94,60.27 49.15,59.49 49.15,58.27 49.28,58.14 50.6,58.14 50.83,58.37 54.15,58.37 55.27,57.25 66.8,57.25 69.27,54.79 69.27,41.25 63.93,35.92 63.93,25.68 64.31,25.3 64.8,25.3 65.18,25.68 65.18,35.48 70.41,40.72 70.41,55.35 66.8,58.95 62.38,58.95
CW on BOTTOM (solid shape): 121.89,53.31 117.06,53.31 117.06,54.58 121.89,54.58
CW on BOTTOM: 118.87,53.31 113.36,53.31 113.36,54.58 118.82,54.58 119.99,55.75 123.65,55.75 123.91,55.49 123.91,54.8 125.35,53.37 126.47,53.37 127.15,52.68 127.15,51.46 126.47,50.77 121.41,50.77
DIM- on BOTTOM: 99.29,15.27 100.94,15.27 102.18,14.02 109.98,14.02 110.29,14.33 110.29,16.21 109.98,16.51 109.98,17.22 111.48,17.22 111.66,17.04 111.66,16.41 111.96,16.1 111.96,12.52 112.45,12.04 114.86,12.04 118.44,15.62 119.58,15.62 123.04,19.08 123.04,24.66 122.66,25.04 120.85,25.04 120.29,25.6 120.29,26.62 120.45,26.77 123.19,26.77 124.99,24.97 124.99,18.97 119.84,13.82 119.13,13.82 115.01,9.7 103.91,9.7 103.3,10.31 100.13,10.31 95.81,5.99 94.11,5.99 94.01,6.1 94.01,9.53 94.13,9.65 97.66,9.65 99.29,11.28
IS on BOTTOM: 90.86,29.69 90.81,29.74 90.81,32.61 91.97,33.78 91.97,46.18 95.1,49.3 95.1,56.49 98.63,60.02 102.36,60.02 104.67,62.33 108.71,62.33 108.86,62.18 108.86,60.91 106.22,60.91 106.05,60.73 104.85,60.73 104.32,60.2 104.32,58.78 103.96,58.42 100.23,58.42 99.47,57.66 99.47,56.26 100.28,55.45 110.72,55.45 112.14,56.87 117.42,56.87 117.53,56.77 117.53,55.65 117.45,55.58 114.81,55.58 114.68,55.45 113.41,55.45 112.93,54.97 112.93,53.52 112.55,53.14 98.96,53.14 98.37,52.55 98.37,50.88 98.96,50.29 120.5,50.29 120.85,49.94 120.85,48.13 97.99,48.13 94.54,44.68 94.54,40.34 94.79,40.08 94.79,39.5 94.54,39.24 94.54,37.29 94.26,37.01 94.26,33.05 92.51,31.29 92.51,29.87 92.33,29.69
RS- on BOTTOM: 99.92,29.9 100.25,30.23 100.25,31.04 100.48,31.27 106.96,31.27 110.24,34.54 113.89,34.54 115.85,36.5 120.68,36.5 124.31,40.13 124.31,44.65 121.97,46.99 121.97,49.68 122.4,50.11 127.56,50.11 128.27,50.83 128.27,50.98 128.09,51.16 127.89,51.16 127.13,50.39 122.07,50.39 121.72,50.04 121.72,47.02 121.06,46.35 121.06,44.63 118.11,41.68 116.05,41.68 115.62,42.11 107.21,42.11 106.86,41.76 106.86,39.32 104.7,37.16 100.61,37.16 99.64,38.13 99.64,38.79 98.86,39.57 96.32,39.57 96.32,37.34 95.28,36.3 95.28,32.46 93.54,30.72 93.54,30.19 92.71,29.36 90.81,29.36 90.81,28.93 93.7,28.93 94.67,29.9
RTN on BOTTOM: 68.73,67.67 39.55,67.67 27.03,55.14 27.03,53.7 26.99,53.66 28.45,52.2 34.77,52.2 35.1,52.53 35.1,53.92 35.41,54.23 36.45,54.23 36.75,53.92 36.75,51.13 36.55,50.93 25.88,50.93 23.85,52.96 23.85,55.52 38.4,70.08 70.26,70.08 72.06,68.28 78.59,68.28 83.71,63.16 83.71,42.49 85.45,40.75 85.45,39.83 83.71,38.09 83.71,14.4 82.73,13.42 82.73,1.17 81.81,0.25 52.07,0.25 51.1,1.22 51.1,13.79 52.04,14.73 63.2,14.73 63.21,14.72 79.03,14.72 80.31,16 80.31,23.65 80.11,23.85 73.25,23.85 72.42,23.01 70.87,23.01 70.87,25.25 72.21,26.59 80.26,26.59 81.15,27.48 81.15,39.19 79.27,41.07 79.27,43.36 80.31,44.4 80.31,62.55 76.96,65.9 70.5,65.9
SEC BIAS 1 on BOTTOM: 95.63,17.09 94.79,16.26 94.79,13.21 95.35,12.65 95.55,12.65 95.55,10.79 94.16,10.79 94.16,11.61 94.08,11.68 91.85,11.68 91.85,13.03 93.17,13.03 93.45,12.75 94.16,12.75 94.28,12.88 94.28,16.28 93.55,17.02 93.55,18.31 93.98,18.75 95.1,18.75 95.63,18.21
V_O on BOTTOM: 121.21,35.59 125.25,39.62 125.25,44.96 122.61,47.6 122.61,49.66 122.68,49.73 128.73,49.73 129.57,48.9 129.57,31.32 128.51,30.26 109.28,30.26 108.71,30.84 108.71,32 110.44,33.73 114.48,33.73 116.33,35.59
WW on BOTTOM (solid shape): 113.3,58.6 108.48,58.6 108.48,59.87 113.3,59.87
WW on BOTTOM: 124.13,61.04 127.08,58.09 127.08,54.89 126.42,54.23 125.37,54.23 124.49,55.12 124.49,55.73 122.78,57.43 112.8,57.43 111.63,58.6 104.78,58.6 104.78,59.87 111.63,59.87 112.8,61.04
Y1Y2 on BOTTOM: 10.22,67.58 3.87,67.58 2.11,69.34 2.11,73.1 3.68,74.68 26.57,74.68 27.46,73.79 27.46,72.54 25.55,70.64 13.28,70.64
N11474232 on BOTTOM: 3.71,52.22 3.71,52.2 0.18,48.67 0.18,33.66 2.46,31.37 2.46,27.56 5.89,24.13 7.09,24.13 7.29,24.33 7.29,26.01 4.47,28.83 4.47,32.51 1.8,35.18 1.8,47.32 5.56,51.08 5.56,51.74 5.08,52.22
N11475153 on BOTTOM: 34.44,56.18 39.45,56.18 40.23,56.97 40.23,62.1 41.81,63.68 66.17,63.68 67.67,62.18 71.75,62.18 72.64,61.29 72.64,38.99 71.83,38.18 68.81,38.18 66.52,35.89 66.52,34.04 66.78,33.78 67.01,33.78 69.8,36.58 72.49,36.58 73.48,35.59 73.48,32.11 73.51,32.08 75.11,32.08 75.64,32.61 75.64,39.12 77.6,41.07 77.6,43.33 75.56,45.36 75.56,63.14 74.6,64.11 69.29,64.11 67.39,66.01 40.49,66.01 29.72,55.24 29.72,53.77 29.77,53.72 31.98,53.72
N11476179 on BOTTOM (solid shape): 40.85,42.87 37.04,42.87 37.04,45.12 35.24,45.12 35.24,47.82 36.9,47.82 36.9,49.77 37,49.77 37.92,50.15 38.3,51.07 38.3,51.17 40.85,51.17
N11476179 on BOTTOM: 46.56,61.82 43.84,61.82 43.48,61.47 43.48,56.39 42.04,54.94 38.94,54.94 38.3,54.31 38.3,45.95 37.08,44.73 37.08,41.91 35.03,39.85 35.03,32.92 35.14,32.8 35.14,31.69 41.17,25.65 41.17,9.91 41.45,9.63 43.94,9.63 45.03,10.72 45.03,18.52 48.63,22.11 48.63,36.79 43.87,41.55 43.87,52.25 46.91,55.3 46.91,61.47
N11479125 on BOTTOM: 48.23,50.93 48.13,51.03 48.13,57 48.26,57.12 49.17,57.12 49.35,56.95 49.35,51.05 49.23,50.93
N11479651 on BOTTOM: 48.59,50.6 49.83,50.6 49.99,50.75 49.99,53.31 50.37,53.7 51.97,53.7 52.55,54.28 52.55,54.89 54.03,56.36 66.37,56.36 68.1,54.64 68.1,44.53 65.51,41.94 52.63,41.94 52.3,42.27 52.3,43.61 52.35,43.66 55.8,43.66 56.18,43.28 60.3,43.28 60.81,43.79 60.81,46.94 60.05,47.7 59.82,47.7 59.66,47.85 59.66,49.23 59.79,49.35 61.42,49.35 61.82,48.95 61.82,48.31 62.76,47.37 64.64,47.37 66.62,49.35 66.62,51.94 66.22,52.35 53.19,52.35 52.64,51.8 52.64,50.23 52.5,50.09 51.31,50.09 51.21,50.19 48.56,50.19 48.49,50.27 48.49,50.5
N11480864 on BOTTOM: 64.57,51.66 64.57,50.09 64.06,49.58 62.89,49.58 62.41,49.1 62.41,48.49 62.95,47.94 64.25,47.94 66.14,49.83 66.14,51.59 66.07,51.66
N11498937 on BOTTOM: 117.17,44.98 117.17,46.93 116.99,47.11 98.48,47.11 95.55,44.19 95.55,41.76 96.04,41.27 104.32,41.27 106.15,43.1 115.54,43.1 115.95,43.51 115.95,44.55 116.15,44.75 116.94,44.75
N11499225 on BOTTOM: 74.8,29.22 75.27,29.69 79.55,29.69 79.63,29.77 79.63,30.1 78.97,30.76 75.36,30.76 74.78,31.34 71.63,31.34 71.5,31.22 71.5,29.54 71.82,29.22
N12102647 on BOTTOM: 50.16,57.07 50.16,54.2 50.24,54.13 51.31,54.13 51.79,54.61 51.79,55.19 53.06,56.46 53.06,57.68 53.01,57.73 50.83,57.73
N12192768 on BOTTOM: 93.29,9.83 91.74,9.83 91.74,6.2 91.87,6.07 93.17,6.07 93.29,6.2

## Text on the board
Ref Des/Silkscreen Bottom: *
Ref Des/Silkscreen Top: 1912 | DER-750 | S/N | REV C | DALI+ | /DIM+ | /DIM- | DALI- | J3 | VOUT | CW | WW
User.5: 3 SLOTS | DELETE THESE HOLES: | 1.  THROUGH HOLES ARE PLATED THROUGH. | EXCEPTIONS WILL BE NOTED IN DRILL CHART "NOTE". | 2.  MATERIAL: BASE MATERIAL LAMINATED EPOXY | UL APPROVED MANUFACTURED SOURCE FOR FR4. | 3.  SOLDER PLATE WILL BE RoHS COMPLIANT. | 4.  SOLDER MASK LPI (LIQUID PHOTO IMAGEABLE) BOTH SIDES. COLOR GREEN. | SOLDER MASK (REGISTRATION) -0/+0.003" | 5.  SILKSCREEN TOP/BOTTOM SIDE. COLOR WHITE. (MIN.WIDTH 0.005" MAX.WIDTH 0.010") | 6.  FINISH TO BE SMOBC. | 7.  LF HASL. | 8.  BOARD DIMENSION +/- 0.005" | 9.  DRILL TOLERANCE +/- 0.003" | 10. TRACE WIDTH UNDER 0.010" +/- 0.002" | TRACE WIDTH OVER 0.011" +/- 0.005" | 11. TRACE SPACE +/- 0.003" | 12. MATERIAL FR4 COPPER 2 OZ BOARD THICKNESS 0.062" | NOTES: UNLESS OTHERWISE SPECIFIED
User.8: FIGURE | FINISHED_SIZE | 30.0 | 38.0 | 40.0 | 44.0 | 46.0 | 48.0 | 50.0 | 52.0 | 55.0 | 60.0 | 63.0 | 67.0 | 173.0 | DRILL CHART: TOP to BOTTOM | ALL UNITS ARE IN MILS | PLATED | QTY | 16 | 18 | 22 | 1 | 2 | 3 | 26 | 10 | 4
